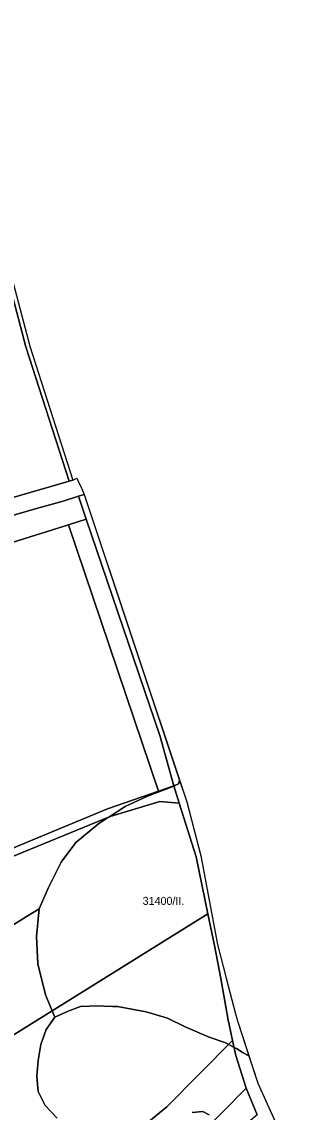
# Model space of a CAD drawing. Extents: x -522079 to -518833, y -1142400 to -1139961.
# Drawn here: x -520002 to -519834, y -1140651 to -1139970 of the extents above; entities that cross this region are included whole.
import ezdxf

# ---------------------------------------------------------------- set-up
doc = ezdxf.new("R2010")
doc.units = 0
for name, color, linetype in [('95560013', 7, 'Continuous'), ('95610013', 7, 'Continuous'), ('95640013', 7, 'Continuous'), ('95660013', 7, 'Continuous')]:
    doc.layers.add(name, color=color, linetype=linetype)

msp = doc.modelspace()

# ---------------------------------------------------------------- linework, layer by layer
at = {"layer": '95560013'}
for points in [[(-520178.95, -1140054.65), (-520121.19, -1140041.17), (-520101.17, -1140033.45), (-520091.68, -1140028.41), (-520082.48, -1140019.36), (-520062.19, -1139990.92), (-520047.4, -1139971.94), (-520042.94, -1139993.02), (-520019.48, -1140099.15), (-519999.86, -1140173.01), (-519972.75, -1140256.9), (-520039.59, -1140276.29), (-520091.03, -1140291.29)], [(-519973.33, -1140284.13), (-519962.19, -1140280.64), (-519916.36, -1140415.97), (-519907.62, -1140447.38), (-519917.2, -1140450.72)], [(-520087.13, -1140319.85), (-519973.33, -1140284.13), (-519917.2, -1140450.72), (-519949.02, -1140461.79), (-520031.39, -1140495.83), (-520041.44, -1140499.76)], [(-519886.24, -1140527.38), (-520082.56, -1140649.64), (-520126.03, -1140587.59), (-520155.91, -1140552.2), (-520104.66, -1140531.14), (-519947.24, -1140466.47), (-519916.36, -1140457.2), (-519904.17, -1140458.14), (-519893.54, -1140491.71)], [(-519911.88, -1140647.84), (-520013.2, -1140730.8), (-520072.01, -1140664.71), (-520082.56, -1140649.64), (-519886.24, -1140527.38), (-519882.2, -1140547.1), (-519878.23, -1140567.62), (-519875.11, -1140585.42), (-519873.69, -1140593.69), (-519873.07, -1140596.47), (-519870.83, -1140606.54)], [(-519862.3, -1140636.3), (-519855.49, -1140652.85), (-519981.63, -1140760.4), (-519991.87, -1140748.27), (-519893.23, -1140667.47)]]:
    msp.add_lwpolyline(points, close=True, dxfattribs=at)
at = {"layer": '95610013'}
msp.add_lwpolyline([(-520037.05, -1140286.83), (-519993.22, -1140274.03), (-519976.66, -1140269.42), (-519967, -1140266.42), (-519962.19, -1140280.64), (-519973.33, -1140284.13), (-520087.13, -1140319.85)], dxfattribs=at)
msp.add_lwpolyline([(-519862.3, -1140636.3), (-519893.23, -1140667.47), (-519991.87, -1140748.27), (-520001.24, -1140755.77), (-520010.06, -1140762.16), (-520068.52, -1140802.68), (-520119.77, -1140834.99), (-520149.6, -1140820.02), (-520083.41, -1140780.15), (-520025.44, -1140739.97), (-520022.9, -1140738.15), (-520013.2, -1140730.8), (-519911.88, -1140647.84), (-519870.83, -1140606.54), (-519868.76, -1140615.85)], close=True, dxfattribs=at)
at = {"layer": '95640013'}
msp.add_lwpolyline([(-520044.21, -1139976.9), (-520040.68, -1139992.3), (-520017.23, -1140098.3), (-519997.42, -1140172.65), (-519970.54, -1140256.24), (-519972.75, -1140256.9), (-519999.86, -1140173.01), (-520019.48, -1140099.15), (-520042.94, -1139993.02), (-520047.4, -1139971.94), (-520045.81, -1139969.91)], close=True, dxfattribs=at)
for points in [[(-520039.59, -1140276.29), (-519972.75, -1140256.9), (-519970.54, -1140256.24), (-519967.99, -1140255.12), (-519967.34, -1140256.59), (-519967.14, -1140257.04), (-519965.23, -1140261.32), (-519965.02, -1140261.78), (-519963.47, -1140265.25), (-519967, -1140266.42), (-519976.66, -1140269.42), (-519993.22, -1140274.03), (-520037.05, -1140286.83)], [(-519855.49, -1140652.85), (-519862.3, -1140636.3), (-519868.76, -1140615.85), (-519870.83, -1140606.54), (-519873.07, -1140596.47), (-519873.69, -1140593.69), (-519875.11, -1140585.42), (-519878.23, -1140567.62), (-519882.2, -1140547.1), (-519886.24, -1140527.38), (-519893.54, -1140491.71), (-519904.17, -1140458.14), (-519907.62, -1140447.38), (-519916.36, -1140415.97), (-519962.19, -1140280.64), (-519967, -1140266.42), (-519963.47, -1140265.25), (-519901.13, -1140452.27), (-519899.47, -1140457.37), (-519890.68, -1140491.02), (-519880.22, -1140546.4), (-519874.89, -1140567.55), (-519868.98, -1140589.75), (-519867.83, -1140594.09), (-519855.18, -1140633.03), (-519833.7, -1140680.7)], [(-520031.39, -1140495.83), (-519949.02, -1140461.79), (-519917.2, -1140450.72), (-519907.62, -1140447.38), (-519904.17, -1140458.14), (-519916.36, -1140457.2), (-519947.24, -1140466.47), (-520104.66, -1140531.14)]]:
    msp.add_lwpolyline(points, dxfattribs=at)
at = {"layer": '95660013'}
for points in [[(-520017.23, -1140098.3), (-519997.42, -1140172.65), (-519970.54, -1140256.24), (-519967.99, -1140255.12), (-519967.34, -1140256.59), (-519967.14, -1140257.04), (-519965.23, -1140261.32), (-519965.02, -1140261.78), (-519963.47, -1140265.25), (-519903.91, -1140443.93), (-519904.58, -1140446.1), (-519906.87, -1140447.15), (-519907.6, -1140447.43), (-519923.94, -1140453.82), (-519938, -1140460.16), (-519948.06, -1140466.81), (-519949.47, -1140467.74), (-519954.25, -1140470.9), (-519968.66, -1140482.76), (-519977.89, -1140494.99), (-519985.65, -1140510.92), (-519991.56, -1140524.26), (-520000, -1140529.44), (-520009.66, -1140535.38)], [(-520009.66, -1140535.38), (-520000, -1140529.44), (-519991.56, -1140524.26), (-519993.3, -1140541.36), (-519992.31, -1140558.59), (-519987.57, -1140578.01), (-519983.42, -1140587.9), (-519981.74, -1140591.91), (-519987.24, -1140599.63), (-519990.53, -1140609), (-519992.18, -1140618.93), (-519993.01, -1140628.85), (-519992.18, -1140638.23), (-519987.78, -1140647.05), (-519980.36, -1140655.04)], [(-519980.36, -1140655.04), (-519987.78, -1140647.05), (-519992.18, -1140638.23), (-519993.01, -1140628.85), (-519992.18, -1140618.93), (-519990.53, -1140609), (-519987.24, -1140599.63), (-519981.74, -1140591.91), (-519973.49, -1140588.05), (-519965.8, -1140585.29), (-519960.2, -1140584.98), (-519955.91, -1140584.75), (-519945.77, -1140585.17), (-519942.72, -1140585.29), (-519924.85, -1140588.6), (-519911.39, -1140592.46), (-519900.39, -1140597.98), (-519885.55, -1140604.32), (-519875.66, -1140607.62), (-519873.22, -1140608.94), (-519869.89, -1140610.74), (-519869.42, -1140611), (-519868.52, -1140611.49), (-519865.59, -1140613.3), (-519864.64, -1140613.89), (-519860.68, -1140616.1), (-519855.18, -1140633.03), (-519839.36, -1140668.14)], [(-519896, -1140651.46), (-519889.4, -1140650.91), (-519885.55, -1140652.84)], [(-519885.55, -1140652.84), (-519889.4, -1140650.91), (-519896, -1140651.46)]]:
    msp.add_lwpolyline(points, dxfattribs=at)
msp.add_lwpolyline([(-519874.89, -1140567.55), (-519868.98, -1140589.75), (-519867.83, -1140594.09), (-519860.68, -1140616.1), (-519864.64, -1140613.89), (-519865.59, -1140613.3), (-519868.52, -1140611.49), (-519869.42, -1140611), (-519869.89, -1140610.74), (-519873.22, -1140608.94), (-519875.66, -1140607.62), (-519885.55, -1140604.32), (-519900.39, -1140597.98), (-519911.39, -1140592.46), (-519924.85, -1140588.6), (-519942.72, -1140585.29), (-519945.77, -1140585.17), (-519955.91, -1140584.75), (-519960.2, -1140584.98), (-519965.8, -1140585.29), (-519973.49, -1140588.05), (-519981.74, -1140591.91), (-519983.42, -1140587.9), (-519987.57, -1140578.01), (-519992.31, -1140558.59), (-519993.3, -1140541.36), (-519991.56, -1140524.26), (-519985.65, -1140510.92), (-519977.89, -1140494.99), (-519968.66, -1140482.76), (-519954.25, -1140470.9), (-519949.47, -1140467.74), (-519948.06, -1140466.81), (-519938, -1140460.16), (-519923.94, -1140453.82), (-519907.6, -1140447.43), (-519906.87, -1140447.15), (-519904.58, -1140446.1), (-519903.91, -1140443.93), (-519901.13, -1140452.27), (-519899.47, -1140457.37), (-519890.68, -1140491.02), (-519880.22, -1140546.4)], close=True, dxfattribs=at)

# ---------------------------------------------------------------- texts
msp.add_text('31400/II.', height=5, rotation=0, dxfattribs=at).set_placement((-519926.99, -1140521.7))

doc.saveas('drawing.dxf')
